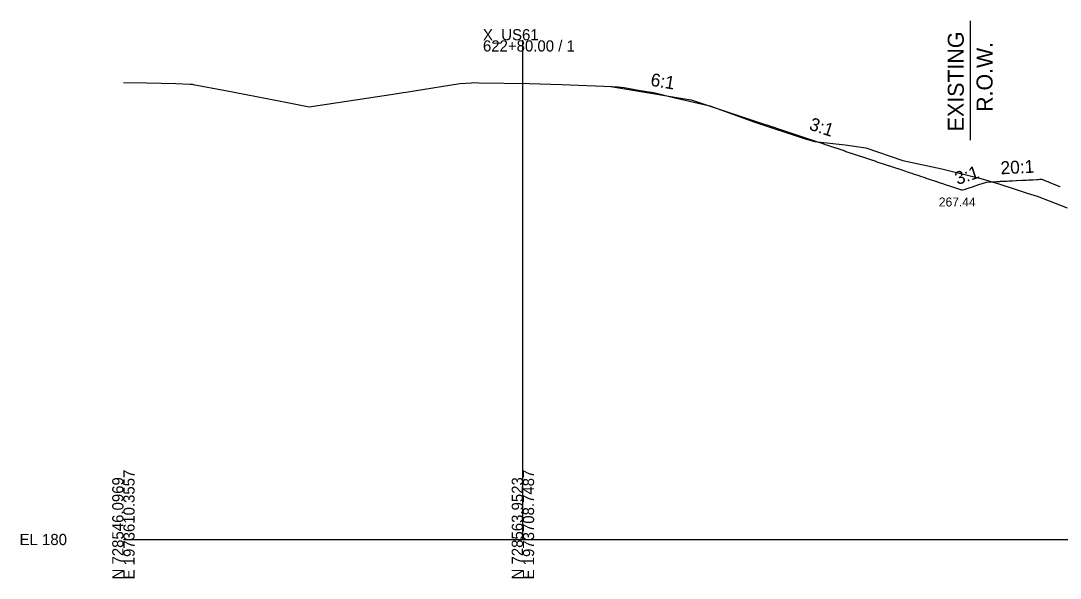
# Model space of a CAD drawing. Extents: x -26 to 1629, y -25 to 9635.
# Drawn here: x -25.7 to 234.5, y 6990.3 to 7129.9 of the extents above; entities that cross this region are included whole.
import ezdxf

# ---------------------------------------------------------------- set-up
doc = ezdxf.new("R2010")
doc.units = 0
for name, color, linetype in [('Default', 7, 'Continuous'), ('Draft_XS_Grid', 7, 'Continuous'), ('DTM CONTOURS_MAJOR', 7, 'Continuous'), ('DTM_X_GROUND', 7, 'Continuous'), ('XS_CELL', 7, 'Continuous'), ('XS_P_GROUND', 7, 'Continuous'), ('XS_P_TX_DCH', 7, 'Continuous'), ('XS_P_TX_FS_BS', 7, 'Continuous'), ('XS_X_ROW', 7, 'Continuous')]:
    doc.layers.add(name, color=color, linetype=linetype)

msp = doc.modelspace()

# ---------------------------------------------------------------- linework, layer by layer
at = {"layer": 'DTM_X_GROUND'}
msp.add_lwpolyline([(0, 7114.46), (5.79, 7114.36), (13.09, 7114.23), (16.71, 7114.06), (16.9, 7114.06), (17.25, 7114.01), (17.49, 7113.95), (25.52, 7112.47), (41.04, 7109.43), (46.51, 7108.32), (68, 7111.59), (70.01, 7111.9), (70.78, 7112.01), (71.75, 7112.17), (72.8, 7112.34), (84.18, 7114.21), (87.15, 7114.38), (87.67, 7114.41), (89.01, 7114.39), (101.53, 7114.2), (109.77, 7113.9), (122.31, 7113.42), (123.84, 7113.34), (125.39, 7113.23), (129.38, 7112.47), (132.75, 7111.9), (137.68, 7110.71), (146.79, 7108.57), (158.03, 7104.49), (170.68, 7100.3), (173.03, 7099.69), (180.66, 7098.81), (185.82, 7098.11), (195.14, 7094.88), (204.91, 7092.82), (214.61, 7090.36), (219.12, 7089.03), (222.94, 7087.78), (226.25, 7086.72), (228.71, 7085.96), (236.21, 7083.05)], dxfattribs=at)
at = {"layer": 'XS_CELL'}
for p, q in [((100, 7000), (100, 7125)), ((0, 7000), (100, 7000)), ((100, 7000), (550, 7000))]:
    msp.add_line(p, q, dxfattribs=at)
at = {"layer": 'XS_P_GROUND'}
for points in [[(122, 7113.44), (142, 7110.1)], [(231.74, 7089.44), (231.65, 7089.48), (231.51, 7089.53), (231.43, 7089.56), (230.35, 7090), (230.27, 7090.03), (230.18, 7090.06), (230, 7090.14), (229.98, 7090.14), (229.84, 7090.13), (229.8, 7090.13), (229.47, 7090.11), (229.39, 7090.11), (228.99, 7090.09), (228.99, 7090.09), (228.8, 7090.08), (228.69, 7090.07), (227.7, 7090.02), (226.65, 7089.97), (226.58, 7089.96), (226.56, 7089.96), (226.08, 7089.94), (226.05, 7089.94), (225.26, 7089.9), (225.23, 7089.9), (224.95, 7089.88), (224.95, 7089.88), (224.88, 7089.88), (223.59, 7089.82), (223.51, 7089.81), (222.53, 7089.76), (222.47, 7089.76), (221.95, 7089.73), (221.71, 7089.72), (221.13, 7089.69), (220.78, 7089.67), (220.41, 7089.66), (220.14, 7089.64), (220.12, 7089.64), (219.51, 7089.61), (219.5, 7089.61), (219.32, 7089.6), (219.32, 7089.6), (218.7, 7089.57), (218.68, 7089.57), (216.03, 7089.44), (216, 7089.44), (215.95, 7089.42), (215.43, 7089.25), (215.4, 7089.24), (214.62, 7088.98), (214.34, 7088.88), (212.19, 7088.17), (211.92, 7088.07), (211.39, 7087.9), (211.13, 7087.81), (210.46, 7087.59), (210, 7087.44), (210, 7087.44), (209.96, 7087.45), (209.78, 7087.51), (209.64, 7087.56), (207.37, 7088.31), (207.09, 7088.41), (205.77, 7088.85), (205.12, 7089.06), (204.29, 7089.34), (204, 7089.44), (203.42, 7089.63), (203.38, 7089.64), (201.82, 7090.16), (201.78, 7090.17), (201.76, 7090.18), (200.99, 7090.44), (200.91, 7090.47), (199.4, 7090.97), (199.21, 7091.03), (197.82, 7091.49), (197.46, 7091.62), (197.03, 7091.76), (196.88, 7091.81), (196.61, 7091.9), (196.26, 7092.01), (196.25, 7092.02), (195.48, 7092.28), (195.46, 7092.28), (193.92, 7092.79), (193.89, 7092.81), (193.12, 7093.06), (193.1, 7093.07), (191.57, 7093.58), (191.53, 7093.59), (190.77, 7093.85), (190.75, 7093.85), (188.47, 7094.61), (188.41, 7094.63), (187.65, 7094.89), (187.63, 7094.89), (186.12, 7095.4), (186.08, 7095.41), (184.57, 7095.91), (184.53, 7095.93), (182.27, 7096.68), (182.21, 7096.7), (180.71, 7097.2), (180.67, 7097.21), (179.92, 7097.46), (179.9, 7097.47), (178.4, 7097.97), (178.36, 7097.98), (176.87, 7098.48), (176.83, 7098.49), (176.09, 7098.74), (176.07, 7098.75), (176.05, 7098.75), (175.69, 7098.87), (175.59, 7098.91), (174.92, 7099.13), (174.89, 7099.14), (173.83, 7099.49), (173.8, 7099.5), (173.06, 7099.75), (173.04, 7099.75), (172.31, 7100), (172.29, 7100), (170.83, 7100.49), (170.79, 7100.51), (170.06, 7100.75), (170.04, 7100.76), (168.58, 7101.24), (168.55, 7101.25), (167.82, 7101.5), (167.8, 7101.5), (166.35, 7101.99), (166.31, 7102), (164.86, 7102.48), (164.82, 7102.49), (164.1, 7102.74), (164.08, 7102.74), (162.64, 7103.22), (162.6, 7103.24), (161.16, 7103.72), (161.12, 7103.73), (160.76, 7103.85), (160.75, 7103.85), (142.45, 7109.95), (142, 7110.1)], [(234.51, 7088.33), (234.48, 7088.34), (234.48, 7088.34), (231.74, 7089.44)]]:
    msp.add_lwpolyline(points, dxfattribs=at)
at = {"layer": 'XS_X_ROW'}
msp.add_line((212, 7129.9), (212, 7100), dxfattribs=at)

# ---------------------------------------------------------------- texts
at = {"layer": 'Default'}
msp.add_text('X', height=0.12, dxfattribs=at).set_placement((141.96, 7110.04))
at = {"layer": 'Draft_XS_Grid'}
msp.add_text('-', height=0.0001, dxfattribs=at).set_placement((0, 7000))
at = {"layer": 'DTM CONTOURS_MAJOR'}
for p in [(121.96, 7113.38), (141.96, 7110.04), (203.96, 7089.38), (215.96, 7089.38), (229.96, 7090.08), (209.96, 7087.38)]:
    msp.add_text('X', height=0.12, dxfattribs=at).set_placement(p)
at = {"layer": 'XS_CELL'}
for s, p in [('X_US61', (90, 7125)), ('622+80.00 / 1', (90, 7122.2)), ('EL 180', (-26, 6998.6))]:
    msp.add_text(s, height=2.8, dxfattribs=at).set_placement(p)
for s, p in [('N 728546.0969', (0, 6990)), ('E 1973610.3557', (2.8, 6990)), ('N 728563.9523', (100, 6990)), ('E 1973708.7487', (102.8, 6990))]:
    msp.add_text(s, height=2.8, rotation=90, dxfattribs=at).set_placement(p)
at = {"layer": 'XS_P_TX_DCH'}
msp.add_text('267.44', height=2.25, dxfattribs=at).set_placement((204.13, 7083.39))
at = {"layer": 'XS_P_TX_FS_BS'}
for s, rotation, p in [('6:1', 350.5377, (131.8, 7113.65)), ('3:1', 341.5651, (171.45, 7102.71)), ('3:1', 18.4349, (208.78, 7088.76)), ('20:1', 2.8624, (219.65, 7091.44))]:
    msp.add_text(s, height=3.24, rotation=rotation, dxfattribs=at).set_placement(p)
at = {"layer": 'XS_X_ROW'}
for s, p in [('EXISTING', (210.37, 7102.23)), ('R.O.W.', (217.57, 7107.08))]:
    msp.add_text(s, height=4, rotation=90, dxfattribs=at).set_placement(p)

doc.saveas('drawing.dxf')
